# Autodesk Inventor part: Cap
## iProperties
Shininess: 77.0
Length Units: 11269
Angle Units: 11279
Time Units: 11290
Mass Units: 11283
Length Display Precision: 3
Angle Display Precision: 2
Created: 2002-02
Part Number: Cap
Document SubType Name: Modeling
Designer: ***
Stock Number: 25
Density: 0.0
Volumn: 0.0
Area: 0.0
PropertySet Name: Model Information
Control State: 0
Master: False
Checked Out: False
Author: ***
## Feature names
1. Extrusion1
2. Extrusion2
3. Hole1
4. Hole2
5. Mirror1
6. Hole3
